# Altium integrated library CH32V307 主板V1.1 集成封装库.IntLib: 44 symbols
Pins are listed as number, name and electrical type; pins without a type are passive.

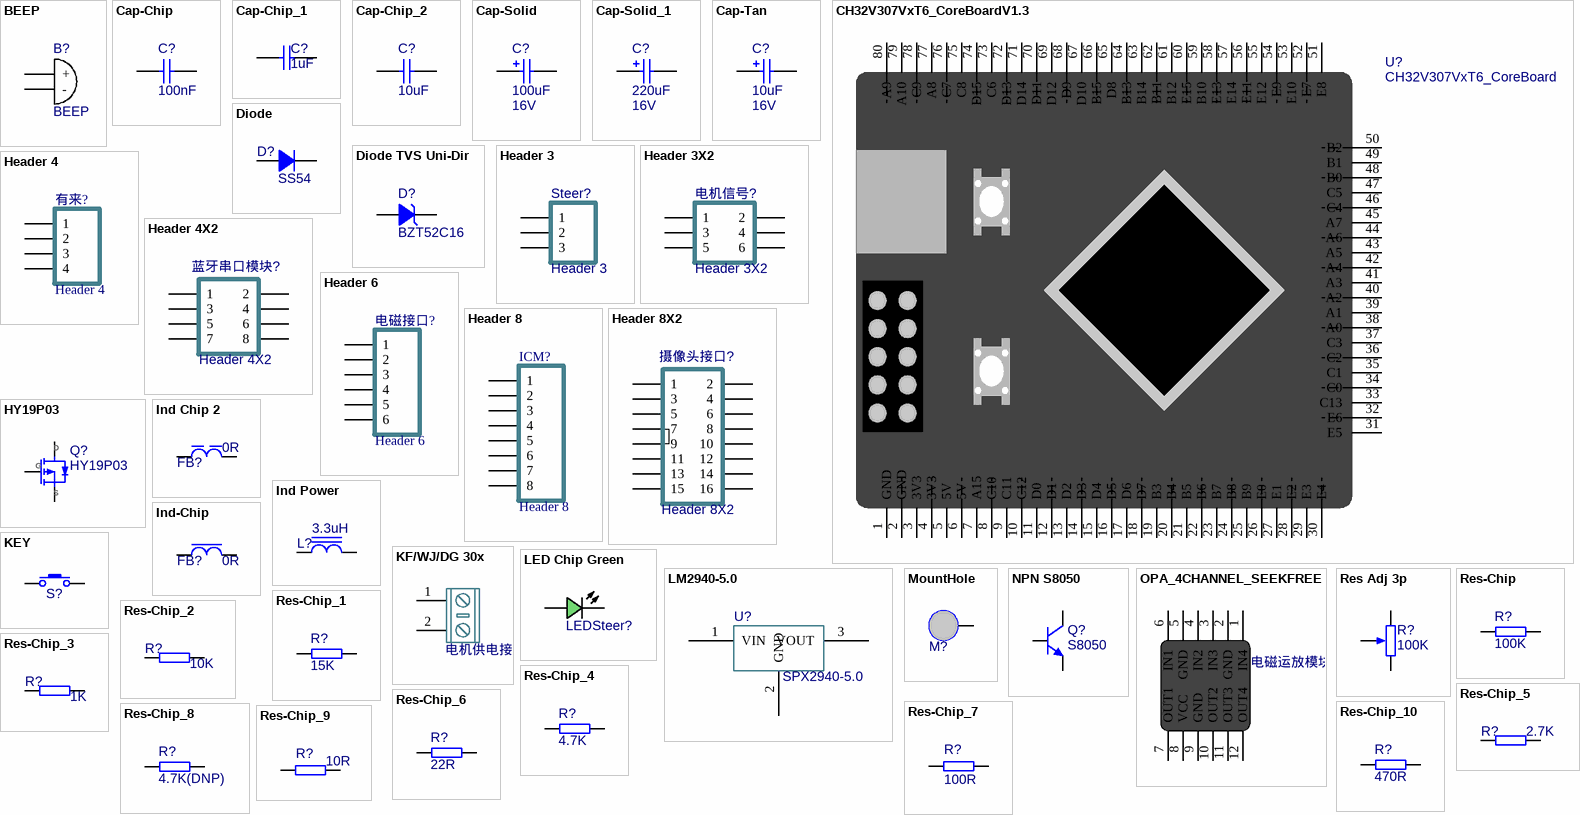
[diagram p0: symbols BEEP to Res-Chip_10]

## BEEP
designator B?
蜂鸣器
footprint BEEP 9x5.5mm
footprint BEEP 12x9.5mm
pins: 1 +, 2 -

## Cap-Chip
designator C?, comment value 100nF  (hidden comment: 100nF ±10% 50V)
贴片电容
footprint CAPC1310[0504]S (Chip Capacitor, 2-Leads, Body 1.17x1.02mm, IPC Medium Density)
footprint CAPC3216[1206]S (Chip Capacitor, Silkscreen Border,2-Leads, Body 3.20x1.60mm, IPC Medium Density)
footprint CAPC3225[1210]S (Chip Capacitor,Silkscreen Border, 2-Leads, Body 3.20x2.50mm, IPC Medium Density)
footprint CAPC4532[1812]S (Chip Capacitor, Silkscreen Border,2-Leads, Body 4.50x3.20mm, IPC Medium Density)
footprint CAPC4564[1825]S (Chip Capacitor,Silkscreen Border, 2-Leads, Body 4.50x6.40mm, IPC Medium Density)
footprint CAPC2012[0805] (Chip Capacitor, 2-Leads, Body 2.00x1.25mm, IPC Medium Density)
footprint CAPC3216[1206] (Chip Capacitor, 2-Leads, Body 3.20x1.60mm, IPC Medium Density)
footprint CAPC3225[1210] (Chip Capacitor, 2-Leads, Body 3.20x2.50mm, IPC Medium Density)
footprint CAPC4532[1812] (Chip Capacitor, 2-Leads, Body 4.50x3.20mm, IPC Medium Density)
footprint CAPC4564[1825] (Chip Capacitor, 2-Leads, Body 4.50x6.40mm, IPC Medium Density)
footprint CAPC1608[0603]-N (Chip Capacitor, 2-Leads, Body 1.60x0.80mm, IPC Medium Density)
footprint CAPC1608[0603]-L (Chip Capacitor, 2-Leads, Body 1.60x0.80mm, IPC Medium Density)
footprint CAPC1608[0603]-M (Chip Capacitor, 2-Leads, Body 1.60x0.80mm, IPC Maximum Density)
footprint CAPC1608[0603]S-L (Chip Capacitor,Silkscreen Border,2-Leads, Body 1.60x0.80mm, IPC Minimum Density)
footprint CAPC1608[0603]S-M (Chip Capacitor,Silkscreen Border,2-Leads, Body 1.60x0.80mm, IPC Maximum Density)
footprint CAPC1608[0603]S-N (Chip Capacitor,Silkscreen Border,2-Leads, Body 1.60x0.80mm, IPC Medium Density)
footprint CAPC1005[0402]-L (Chip Capacitor,Silkscreen border, 2-Leads, Body 1.00x0.50mm, IPC Medium Density)
footprint CAPC1005[0402]-M (Chip Capacitor,Silkscreen border, 2-Leads, Body 1.00x0.50mm, IPC Medium Density)
footprint CAPC1005[0402]-N (Chip Capacitor,Silkscreen border, 2-Leads, Body 1.00x0.50mm, IPC Medium Density)
footprint CAPC1005[0402]S-L (Chip Capacitor,Silkscreen border, 2-Leads, Body 1.00x0.50mm, IPC Medium Density)
footprint CAPC1005[0402]S-M (Chip Capacitor,Silkscreen border, 2-Leads, Body 1.00x0.50mm, IPC Medium Density)
footprint CAPC1005[0402]S-N (Chip Capacitor,Silkscreen border, 2-Leads, Body 1.00x0.50mm, IPC Medium Density)
footprint CAPC2012[0805]S-L (Chip Capacitor,Silkscreen Border, 2-Leads, Body 2.00x1.25mm, IPC Maximum Density)
footprint CAPC2012[0805]S-M (Chip Capacitor,Silkscreen Border, 2-Leads, Body 2.00x1.25mm, IPC Minimum Density)
footprint CAPC2012[0805]S-N (Chip Capacitor,Silkscreen Border, 2-Leads, Body 2.00x1.25mm, IPC Medium Density)
pins: 1, 2

## Cap-Chip_1
designator C?, comment value 1uF  (hidden comment: 1uF ±10% 50V)
贴片电容
footprint CAPC1310[0504]S (Chip Capacitor, 2-Leads, Body 1.17x1.02mm, IPC Medium Density)
footprint CAPC3216[1206]S (Chip Capacitor, Silkscreen Border,2-Leads, Body 3.20x1.60mm, IPC Medium Density)
footprint CAPC3225[1210]S (Chip Capacitor,Silkscreen Border, 2-Leads, Body 3.20x2.50mm, IPC Medium Density)
footprint CAPC4532[1812]S (Chip Capacitor, Silkscreen Border,2-Leads, Body 4.50x3.20mm, IPC Medium Density)
footprint CAPC4564[1825]S (Chip Capacitor,Silkscreen Border, 2-Leads, Body 4.50x6.40mm, IPC Medium Density)
footprint CAPC2012[0805] (Chip Capacitor, 2-Leads, Body 2.00x1.25mm, IPC Medium Density)
footprint CAPC3216[1206] (Chip Capacitor, 2-Leads, Body 3.20x1.60mm, IPC Medium Density)
footprint CAPC3225[1210] (Chip Capacitor, 2-Leads, Body 3.20x2.50mm, IPC Medium Density)
footprint CAPC4532[1812] (Chip Capacitor, 2-Leads, Body 4.50x3.20mm, IPC Medium Density)
footprint CAPC4564[1825] (Chip Capacitor, 2-Leads, Body 4.50x6.40mm, IPC Medium Density)
footprint CAPC1608[0603]-N (Chip Capacitor, 2-Leads, Body 1.60x0.80mm, IPC Medium Density)
footprint CAPC1608[0603]-L (Chip Capacitor, 2-Leads, Body 1.60x0.80mm, IPC Medium Density)
footprint CAPC1608[0603]-M (Chip Capacitor, 2-Leads, Body 1.60x0.80mm, IPC Maximum Density)
footprint CAPC1608[0603]S-L (Chip Capacitor,Silkscreen Border,2-Leads, Body 1.60x0.80mm, IPC Minimum Density)
footprint CAPC1608[0603]S-M (Chip Capacitor,Silkscreen Border,2-Leads, Body 1.60x0.80mm, IPC Maximum Density)
footprint CAPC1608[0603]S-N (Chip Capacitor,Silkscreen Border,2-Leads, Body 1.60x0.80mm, IPC Medium Density)
footprint CAPC1005[0402]-L (Chip Capacitor,Silkscreen border, 2-Leads, Body 1.00x0.50mm, IPC Medium Density)
footprint CAPC1005[0402]-M (Chip Capacitor,Silkscreen border, 2-Leads, Body 1.00x0.50mm, IPC Medium Density)
footprint CAPC1005[0402]-N (Chip Capacitor,Silkscreen border, 2-Leads, Body 1.00x0.50mm, IPC Medium Density)
footprint CAPC1005[0402]S-L (Chip Capacitor,Silkscreen border, 2-Leads, Body 1.00x0.50mm, IPC Medium Density)
footprint CAPC1005[0402]S-M (Chip Capacitor,Silkscreen border, 2-Leads, Body 1.00x0.50mm, IPC Medium Density)
footprint CAPC1005[0402]S-N (Chip Capacitor,Silkscreen border, 2-Leads, Body 1.00x0.50mm, IPC Medium Density)
footprint CAPC2012[0805]S-L (Chip Capacitor,Silkscreen Border, 2-Leads, Body 2.00x1.25mm, IPC Maximum Density)
footprint CAPC2012[0805]S-M (Chip Capacitor,Silkscreen Border, 2-Leads, Body 2.00x1.25mm, IPC Minimum Density)
footprint CAPC2012[0805]S-N (Chip Capacitor,Silkscreen Border, 2-Leads, Body 2.00x1.25mm, IPC Medium Density)
pins: 1, 2

## Cap-Chip_2
designator C?, comment value 10uF  (hidden comment: 10uF ±10% 50V)
贴片电容
footprint CAPC1310[0504]S (Chip Capacitor, 2-Leads, Body 1.17x1.02mm, IPC Medium Density)
footprint CAPC3216[1206]S (Chip Capacitor, Silkscreen Border,2-Leads, Body 3.20x1.60mm, IPC Medium Density)
footprint CAPC3225[1210]S (Chip Capacitor,Silkscreen Border, 2-Leads, Body 3.20x2.50mm, IPC Medium Density)
footprint CAPC4532[1812]S (Chip Capacitor, Silkscreen Border,2-Leads, Body 4.50x3.20mm, IPC Medium Density)
footprint CAPC4564[1825]S (Chip Capacitor,Silkscreen Border, 2-Leads, Body 4.50x6.40mm, IPC Medium Density)
footprint CAPC2012[0805] (Chip Capacitor, 2-Leads, Body 2.00x1.25mm, IPC Medium Density)
footprint CAPC3216[1206] (Chip Capacitor, 2-Leads, Body 3.20x1.60mm, IPC Medium Density)
footprint CAPC3225[1210] (Chip Capacitor, 2-Leads, Body 3.20x2.50mm, IPC Medium Density)
footprint CAPC4532[1812] (Chip Capacitor, 2-Leads, Body 4.50x3.20mm, IPC Medium Density)
footprint CAPC4564[1825] (Chip Capacitor, 2-Leads, Body 4.50x6.40mm, IPC Medium Density)
footprint CAPC1608[0603]-N (Chip Capacitor, 2-Leads, Body 1.60x0.80mm, IPC Medium Density)
footprint CAPC1608[0603]-L (Chip Capacitor, 2-Leads, Body 1.60x0.80mm, IPC Medium Density)
footprint CAPC1608[0603]-M (Chip Capacitor, 2-Leads, Body 1.60x0.80mm, IPC Maximum Density)
footprint CAPC1608[0603]S-L (Chip Capacitor,Silkscreen Border,2-Leads, Body 1.60x0.80mm, IPC Minimum Density)
footprint CAPC1608[0603]S-M (Chip Capacitor,Silkscreen Border,2-Leads, Body 1.60x0.80mm, IPC Maximum Density)
footprint CAPC1608[0603]S-N (Chip Capacitor,Silkscreen Border,2-Leads, Body 1.60x0.80mm, IPC Medium Density)
footprint CAPC1005[0402]-L (Chip Capacitor,Silkscreen border, 2-Leads, Body 1.00x0.50mm, IPC Medium Density)
footprint CAPC1005[0402]-M (Chip Capacitor,Silkscreen border, 2-Leads, Body 1.00x0.50mm, IPC Medium Density)
footprint CAPC1005[0402]-N (Chip Capacitor,Silkscreen border, 2-Leads, Body 1.00x0.50mm, IPC Medium Density)
footprint CAPC1005[0402]S-L (Chip Capacitor,Silkscreen border, 2-Leads, Body 1.00x0.50mm, IPC Medium Density)
footprint CAPC1005[0402]S-M (Chip Capacitor,Silkscreen border, 2-Leads, Body 1.00x0.50mm, IPC Medium Density)
footprint CAPC1005[0402]S-N (Chip Capacitor,Silkscreen border, 2-Leads, Body 1.00x0.50mm, IPC Medium Density)
footprint CAPC2012[0805]S-L (Chip Capacitor,Silkscreen Border, 2-Leads, Body 2.00x1.25mm, IPC Maximum Density)
footprint CAPC2012[0805]S-M (Chip Capacitor,Silkscreen Border, 2-Leads, Body 2.00x1.25mm, IPC Minimum Density)
footprint CAPC2012[0805]S-N (Chip Capacitor,Silkscreen Border, 2-Leads, Body 2.00x1.25mm, IPC Medium Density)
pins: 1, 2

## Cap-Solid
designator C?, comment value 100uF  Voltage: 16V  (hidden comment: 100uF 16V)
Polarized Capacitor (Radial)
footprint CAPS4 (Solid Electorlytic Capacitor, B-type Footprint, 4mm Diameter, 5.5mm Height)
footprint CAPS5 (Solid Electorlytic Capacitor, D-type Footprint, 5mm Diameter, 5.5mm Height)
footprint CAPS6.3 (Solid Electorlytic Capacitor, E-type Footprint, 6.3mm Diameter, 5.5mm Height)
footprint CAPS8 (Solid Electorlytic Capacitor, G-type Footprint, 8mm Diameter, 10mm Height)
footprint CAPS10 (Solid Electorlytic Capacitor, H-type Footprint, 10mm Diameter, 10mm Height)
pins: 1, 2

## Cap-Solid_1
designator C?, comment value 220uF  Voltage: 16V  (hidden comment: 220uF 16V)
Polarized Capacitor (Radial)
footprint CAPS4 (Solid Electorlytic Capacitor, B-type Footprint, 4mm Diameter, 5.5mm Height)
footprint CAPS5 (Solid Electorlytic Capacitor, D-type Footprint, 5mm Diameter, 5.5mm Height)
footprint CAPS6.3 (Solid Electorlytic Capacitor, E-type Footprint, 6.3mm Diameter, 5.5mm Height)
footprint CAPS8 (Solid Electorlytic Capacitor, G-type Footprint, 8mm Diameter, 10mm Height)
footprint CAPS10 (Solid Electorlytic Capacitor, H-type Footprint, 10mm Diameter, 10mm Height)
pins: 1, 2

## Cap-Tan
designator C?, comment value 10uF  Voltage: 16V  (hidden comment: 10uF 16V)
Tantalum Capacitor
footprint CAPT3216 (Molded (Tantalum) Capacitor, 2-Leads, Body 3.20x1.60mm, IPC Medium Density)
footprint CAPT3528 (Molded Tantalum Capacitor, 2-Leads, Body 3.50x2.80mm, IPC Medium Density)
footprint CAPT6032 (Molded Tantalum Capacitor, 2-Leads, Body 6.00x3.20mm, IPC Medium Density)
footprint CAPT7343 (Molded Tantalum Capacitor, 2-Leads, Body 7.30x4.30mm, IPC Medium Density)
footprint CAPT7361 (Molded Tantalum Capacitor, 2-Leads, Body 7.30x6.10mm, IPC Medium Density)
pins: 1, 2

## CH32V307VxT6_CoreBoardV1.3
designator U?, comment CH32V307VxT6_CoreBoard
CH32V307VxT6_CoreBoardV1.3
footprint CH32V307VxT6_CoreBoard (逐飞科技CH32V307VxT6核心板)
pins: 1 GND, 2 GND, 3 3V3, 4 3V3, 5 5V, 6 5V, 7 A15, 8 C10, 9 C11, 10 C12, 11 D0, 12 D1, 13 D2, 14 D3, 15 D4, 16 D5, 17 D6, 18 D7, 19 B3, 20 B4, 21 B5, 22 B6, 23 B7, 24 B8, 25 B9, 26 E0, 27 E1, 28 E2, 29 E3, 30 E4, 31 E5, 32 E6, 33 C13, 34 C0, 35 C1, 36 C2, 37 C3, 38 A0, 39 A1, 40 A2, 41 A3, 42 A4, 43 A5, 44 A6, 45 A7, 46 C4, 47 C5, 48 B0, 49 B1, 50 B2, 51 E8, 52 E7, 53 E10, 54 E9, 55 E12, 56 E11, 57 E14, 58 E13, 59 B10, 60 E15, 61 B12, 62 B11, 63 B14, 64 B13, 65 D8, 66 B15, 67 D10, 68 D9, 69 D12, 70 D11, 71 D14, 72 D13, 73 C6, 74 D15, 75 C8, 76 C7, 77 A8, 78 C9, 79 A10, 80 A9

## Diode
designator D?, comment SS54
普通二极管 Diode; Imax: 500mA
footprint SMB[DO-214AA] (Molded Diode, 2-Leads, Body 5.30x3.55mm, IPC Medium Density)
footprint SMC[DO-214AB] (Molded Diode, 2-Leads, Body 7.94x5.90mm, IPC Medium Density)
footprint SMA[DO-214AC] (Molded Diode, 2-Leads, Body 5.00x2.49mm, IPC Medium Density)
footprint SOD-123-FL (SOD Diode;2.70mm W X 1.60mm L X 1.35mm H body)
footprint SOD-123-M (SOD Diode;2.70mm W X 1.60mm L X 1.35mm H body)
footprint SOD-323 (SOD Diode;1.65mm W X 1.24mm L X 1.16mm H body)
footprint SOD-523-L (SODFL Diode;1.20mm W X 0.80mm L X 0.70mm H body)
footprint SOD-523-M (SODFL Diode;1.20mm W X 0.80mm L X 0.70mm H body)
footprint SOD-123-L (SOD Diode;2.70mm W X 1.60mm L X 1.35mm H body)
pins: A, K

## Diode TVS Uni-Dir
designator D?, comment BZT52C16
TRANSIENT VOLTAGE  SUPPRESSOR DIODE; Imax: 500mA
footprint DO-41 (Diode,Axial;8.30mm C X 0.70mm W 4.60mm L X 2.40mm Dia)
footprint SMA[DO-214AC] (Molded Diode, 2-Leads, Body 5.00x2.49mm, IPC Medium Density)
footprint SMB[DO-214AA] (Molded Diode, 2-Leads, Body 5.30x3.55mm, IPC Medium Density)
footprint SMC[DO-214AB] (Molded Diode, 2-Leads, Body 7.94x5.90mm, IPC Medium Density)
footprint SOD-123-FL (SOD Diode;2.70mm W X 1.60mm L X 1.35mm H body)
footprint SOD-323 (SOD Diode;1.65mm W X 1.24mm L X 1.16mm H body)
footprint SOD-123-L (SOD Diode;2.70mm W X 1.60mm L X 1.35mm H body)
footprint SOD-523-L (SODFL Diode;1.20mm W X 0.80mm L X 0.70mm H body)
footprint SOD-123-M (SOD Diode;2.70mm W X 1.60mm L X 1.35mm H body)
footprint SOD-523-M (SODFL Diode;1.20mm W X 0.80mm L X 0.70mm H body)
pins: A, K

## Header 3
designator Steer?
Header, 3-Pin
footprint HDR1X3 (Connector; Header; 3 Position)
signal-integrity model Connector
footprint XH2.54-3
footprint VH3.96-3
footprint PH2.0-3
footprint GH1.25T-3P (线对板 1.25mm间距 3P 表贴连接座)
footprint XH2.54-3-L (XH2.54 卧式 三针白色插座)
footprint XH2.54-WS-3P (长：12.5mm，宽：8mm，高：6.1mm   淘宝ID:黄晶宝石   店铺网址:https://shop463601444.taobao.com)
pins: 1, 2, 3

## Header 3X2
designator 电机信号?
Header, 3-Pin, Dual row
signal-integrity model Connector
footprint HDR2X3 (Connector; Header; 3x2 Position)
footprint HDR2X3-M-SMT
footprint HDR2X3-F-SMT (2x3pin, 2.54mm间距, SMT, 直排母)
pins: 1, 2, 3, 4, 5, 6

## Header 4
designator 有来?
Header, 4-Pin
signal-integrity model Connector
footprint HDR1X4 (Connector; Header; 4 Position)
footprint XH2.54-4
footprint VH3.96-4
footprint PH2.0-4 (PH2.0 4 pin)
footprint HDR1X4_Download (4pin下载接口)
footprint HDR1X4-NS (2.54间距, 4Pin, 直插排针, 无丝印)
footprint GH1.25T-4P (线对板 1.25mm间距 4P 表贴连接座)
footprint XH2.54-4-L (XH2.54 卧式 四针白色插座)
footprint HDR1X4-TP (2.54mm间距,表面焊盘)
footprint HDR1X4-TP-NS (2.54mm间距,表面焊盘 无丝印)
pins: 1, 2, 3, 4

## Header 4X2
designator 蓝牙串口模块?
Header, 4-Pin, Dual row
footprint HDR2X4 (Connector; Header; 4x2 Position)
signal-integrity model Connector
footprint Female-Header-2.54-SMD-8
footprint HDR2X4-M-SMT (2x4pin, 2.54mm间距, SMT, 直排针)
footprint HDR2X4-F-SMT (2x4pin, 2.54mm间距, SMT, 直排母)
pins: 1, 2, 3, 4, 5, 6, 7, 8

## Header 6
designator 电磁接口?
Header, 6-Pin
footprint HDR1X6 (Connector; Header; 6 Position)
signal-integrity model Connector
footprint PH2.0-6 (PH2.0 9 pin)
footprint XH2.54-6
footprint VH3.96-6
footprint GH1.25T-6P (线对板 1.25mm间距 6P 表贴连接座)
footprint ZH1.5-WF-6P
pins: 1, 2, 3, 4, 5, 6

## Header 8
designator ICM?
Header, 8-Pin
footprint HDR1X8 (Connector; Header; 8 Position)
signal-integrity model Connector
footprint XH2.54V-8
footprint XH2.54-8
footprint VH3.96-8
footprint PH2.0-8 (PH2.0 9 pin)
footprint GH1.25T-8P (线对板 1.25mm间距 8P 表贴连接座)
pins: 1, 2, 3, 4, 5, 6, 7, 8

## Header 8X2
designator 摄像头接口?
Header, 8-Pin, Dual row
footprint HDR2X8 (Connector; Header; 8x2 Position)
signal-integrity model Connector
footprint IDC2.54-16
footprint HDR2X8-M-SMT (2x8pin, 2.54mm间距, SMT, 直排针)
footprint HDR2X8-F-SMT (2x8pin, 2.54mm间距, SMT, 直排母)
pins: 1, 2, 3, 4, 5, 6, 7, 8, 9, 10, 11, 12, 13, 14, 15, 16

## HY19P03
designator Q?
HY19P03 P-Channel MOSFET
footprint TO-252AA (D-PAK, 4-Leads, Body 6.1x6.5mm, Pitch 2.28mm, Lead Span 9.8mm, IPC Low Density)
pins: 1 D, 2 G, 3 S

## Ind Chip 2
designator FB?, comment 0R
Chip Inductor, Ferrite-Core, Silkscreen Border; Imax: 50mA; DCR: .1m
footprint INDC2012[0805]S (Chip Inductor,Silkscreen Border, 2-Leads, Body 2.00x0.90mm, IPC Medium Density)
pins: 1, 2

## Ind Power
designator L?, comment 3.3uH
Power Inductor, Ferrite-Core; Imax: 50mA; DCR: .5m
footprint CD31
footprint CD32
footprint CD42
footprint CD43
footprint CD52
footprint CD53
footprint CD54
footprint CD73
footprint CD75
footprint CD104
footprint CD105
footprint CD106
footprint 127 Shielded 12.5*12.5*7 (12.5mmx12.5mmx7mm 屏蔽电感)
footprint 0630 TPC 7*7*3 (12mmx12mmx6.5mm 一体成型功率电感)
footprint 1050 TPC 10*10*5 (12mmx12mmx6.5mm 一体成型功率电感)
footprint 1265 TPC 12*12*6.5 (12mmx12mmx6.5mm 一体成型功率电感)
pins: 1, 2

## Ind-Chip
designator FB?, comment 0R
Chip Inductor, Ferrite-Core, Silkscreen Border; Imax: 500mA; DCR: .1m
footprint INDC1608[0603]S (Not in IPC, Chip Inductor,Silkscreen Border, 2-Leads, Body 1.60x0.80mm, IPC Medium Density)
footprint INDC2012[0805]S (Chip Inductor,Silkscreen Border, 2-Leads, Body 2.00x0.90mm, IPC Medium Density)
footprint INDC3216[1206]S (Chip Inductor,Silkscreen Border, 2-Leads, Body 3.20x1.60mm, IPC Medium Density)
footprint INDC4509[1806]S (Chip Inductor,Silkscreen Border, 2-Leads, Body 4.50x0.90mm, IPC Medium Density)
footprint INDC1005[0402] (Chip Inductor, 2-Leads, Body 1.00x0.50mm, IPC Medium Density)
footprint INDC1608[0603] (Chip Inductor, 2-Leads, Body 1.60x0.80mm, IPC Medium Density)
footprint INDC2012[0805] (Chip Inductor, 2-Leads, Body 2.00x0.90mm, IPC Medium Density)
footprint INDC3216[1206] (Chip Inductor, 2-Leads, Body 3.20x1.60mm, IPC Medium Density)
footprint INDC3225[1210] (Capacitor,non-polarized,Chip;3.20mm L X 2.50mm W X 1.35mm H)
footprint INDC3216[1206] (Chip Inductor, 2-Leads, Body 3.20x1.60mm, IPC Medium Density)
pins: 1, 2

## KEY
designator S?, comment Button  (value not drawn)
按键
footprint KEY-2-SMD-3*4 (龟仔按键 3*4)
footprint KEY-4-DIP-6*6 (6x6 直插按键封装)
footprint PTS810-3*4-CurvePin (3*4 白色 汽车遥控器贴片按键 包脚)
footprint KEY-2-SMD-3*6-L (3x6贴片按键 高密度)
footprint KEY-2-SMD-3*6-M (3x6贴片按键 低密度)
footprint KEY-4-SMD-6*6 (6x6贴片按键封装)
footprint KEY-2-SMD-Side-3*6*3.5 (7.6x3.5mm 侧按按键)
footprint KEY-4-SMD-12*12 (6x6贴片按键封装)
footprint TS-1809SM-A (3*3.5 贴片4脚按键 (TS-A015))
pins: 1, 2

## KF/WJ/DG 30x
designator DCOUT?, comment 电机供电接口
接线端子 2Pin
footprint KF/WJ/DG 301-2p-5.0mm (2P 5.08mm间距 接线端子)
pins: 1, 2

## LED Chip Green
designator LEDSteer?, comment 翠绿贴片LED  (value not drawn)
footprint LEDC1608(0603) (LED,Chip;1.60mm L X 0.80mm W X 0.80mm H)
footprint LEDC2012(0805) (LED,Chip;2.00mm L X 1.25mm W X 1.20mm H)
footprint LEDC3216(1206) (LED,Chip;3.20mm L X 1.60mm W X 1.30mm H)
footprint LEDC1608(0603)-L (LED,Chip;1.60mm L X 0.80mm W X 0.80mm H)
footprint LEDC2012(0805)-L (LED,Chip;2.00mm L X 1.25mm W X 1.20mm H)
footprint LEDC3216(1204) (LED,Chip;3.20mm L X 1.60mm W X 1.30mm H)
footprint LEDC3528-2 (3528 2脚 贴片LED)
pins: A, C

## LM2940-5.0
designator U?, comment SPX2940-5.0
5V LDO TO-263-3
footprint TO-263-3
pins: 1 VIN, 2 GND, 3 VOUT

## MountHole
designator M?  (value not drawn)  (no BOM)
固定孔
footprint M3-MountHole
footprint M3-MountSlot (M3-MountHole)
footprint M3-MountHole-Plated (M3-MountHole)
footprint M3-MountSlot-Plated (M3-MountHole)
footprint M3-MountHole-4mm (M3-MountHole)
footprint M3-MountHole-5mm (M3-MountHole)
footprint M3-MountHole-6mm (M3-MountHole)
footprint M3-MountHole-7mm (M3-MountHole)
footprint M3-MountHole-8mm (M3-MountHole)
footprint M3-MountHole-9mm (M3-MountHole)
footprint M3-MountHole-10mm (M3-MountHole)
footprint M3-MountHole-11mm (M3-MountHole)
footprint M3-MountHole-12mm (M3-MountHole)
footprint M3-MountHole-13mm (M3-MountHole)
footprint M3-MountHole-14mm (M3-MountHole)
footprint M3-MountHole-15mm (M3-MountHole)
footprint M3-MountHole-16mm (M3-MountHole)
footprint M3-MountHole-17mm (M3-MountHole)
footprint M3-MountHole-18mm (M3-MountHole)
footprint M3-MountHole-19mm (M3-MountHole)
footprint M3-MountHole-20mm (M3-MountHole)
footprint M3-MountHole-Plated-4MM (M3-MountHole)
footprint M3-MountHole-Plated-5MM (M3-MountHole)
footprint M3-MountHole-Plated-6MM (M3-MountHole)
footprint M3-MountHole-Plated-7MM (M3-MountHole)
footprint M3-MountHole-Plated-8MM (M3-MountHole)
footprint M3-MountHole-Plated-9MM (M3-MountHole)
footprint M3-MountHole-Plated-10MM (M3-MountHole)
footprint M3-MountHole-Plated-11MM (M3-MountHole)
footprint M3-MountHole-Plated-12MM (M3-MountHole)
footprint M3-MountHole-Plated-13MM (M3-MountHole)
footprint M3-MountHole-Plated-14MM (M3-MountHole)
footprint M3-MountHole-Plated-15MM (M3-MountHole)
footprint M3-MountHole-Plated-16MM (M3-MountHole)
footprint M3-MountHole-Plated-17MM (M3-MountHole)
footprint M3-MountHole-Plated-18MM (M3-MountHole)
footprint M3-MountHole-Plated-19MM (M3-MountHole)
footprint M3-MountHole-Plated-20MM (M3-MountHole)
pins: 1

## NPN S8050
designator Q?, comment S8050
Discrete NPN Bipolar Transistor
footprint SOT-23 (SOT23, 3-Leads, Body 2.90x2.40mm, Pitch 0.95mm, IPC Medium Density)
pins: 1 B, 2 E, 3 C

## OPA_4CHANNEL_SEEKFREE
designator 电磁运放模块?, comment OPA_MOD  (value not drawn)  (no BOM)
OPA module
footprint SEEKFREE_4CHANEL_OPAMOD
pins: 1 IN4, 2 GND, 3 IN3, 4 IN2, 5 GND, 6 IN1, 7 OUT1, 8 VCC, 9 GND, 10 OUT2, 11 OUT3, 12 OUT4

## Res Adj 3p
designator R?, comment 100K
可调电阻
footprint RESPOT3296 (Precise Multi-Winding Adjustable Resistor)
footprint RESPOTSMALL (Small Pot)
pins: 1 TOP, 2 BOT, ADJ

## Res-Chip
designator R?, comment value 100K  (hidden comment: 100K ±1%)
贴片电阻
footprint RESC3225[1210]S (Silkscreen Outside, Chip Resistor, 2-Leads, Body 3.20x2.49mm, IPC Medium Density)
footprint RESC5025[2010]S (Silkscreen Outside, Chip Resistor, 2-Leads, Body 5.00x2.50mm, IPC Medium Density)
footprint RESC6332[2512]S (Silkscreen Outside, Chip Resistor, 2-Leads, Body 6.30x3.20mm, IPC Medium Density)
footprint RESC5025[2010] (Chip Resistor, 2-Leads, Body 5.00x2.50mm, IPC Medium Density)
footprint RESC6332[2512] (Chip Resistor, 2-Leads, Body 6.30x3.20mm, IPC Medium Density)
footprint RESC3225[1210] (Chip Resistor, 2-Leads, Body 3.20x2.49mm, IPC Medium Density)
footprint RESC3216[1206] (Chip Resistor, 2-Leads, Body 3.20x1.60mm, IPC Medium Density)
footprint RESC2012[0805] (Chip Resistor, 2-Leads, Body 2.00x1.25mm, IPC Medium Density)
footprint RESC1608[0603]-M (Chip Resistor, 2-Leads, Body 1.60x0.82mm, IPC Maximum Density)
footprint RESC1608[0603]-L (Chip Resistor, 2-Leads, Body 1.60x0.82mm, IPC Minimum Density)
footprint RESC1608[0603]-N (Chip Resistor, 2-Leads, Body 1.60x0.82mm, IPC Medium Density)
footprint RESC1608[0603]S-L (Silkscreen Outside, Chip Resistor, 2-Leads, Body 1.60x0.82mm, IPC Minimum Density)
footprint RESC1608[0603]S-M (Silkscreen Outside, Chip Resistor, 2-Leads, Body 1.60x0.82mm, IPC Maximum Density)
footprint RESC1608[0603]S-N (Silkscreen Outside, Chip Resistor, 2-Leads, Body 1.60x0.82mm, IPC Medium Density)
footprint RESC1005[0402]-L (0402贴片电阻 无丝印 2脚 1.00x0.50mm，IPC高密度)
footprint RESC1005[0402]-N (0402贴片电阻 无丝印 2脚 1.00x0.50mm，IPC中密度)
footprint RESC1005[0402]-M (0402贴片电阻 无丝印 2脚 1.00x0.50mm，IPC低密度)
footprint RESC1005[0402]S-L (0402贴片电阻 有丝印 2脚 1.00x0.50mm，IPC高密度)
footprint RESC1005[0402]S-M (0402贴片电阻 有丝印 2脚 1.00x0.50mm，IPC低密度)
footprint RESC1005[0402]S-N (0402贴片电阻 有丝印 2脚 1.00x0.50mm，IPC中等密度)
footprint RESC2012[0805]S-L (Silkscreen Outside, Chip Resistor, 2-Leads, Body 2.00x1.25mm, IPC Medium Density)
footprint RESC2012[0805]S-M (Silkscreen Outside, Chip Resistor, 2-Leads, Body 2.00x1.25mm, IPC Medium Density)
footprint RESC2012[0805]S-N (Silkscreen Outside, Chip Resistor, 2-Leads, Body 2.00x1.25mm, IPC Medium Density)
footprint RESC3216[1206]S-L (Silkscreen Outside, Chip Resistor, 2-Leads, Body 3.20x1.60mm, IPC Medium Density)
footprint RESC3216[1206]S-M (Silkscreen Outside, Chip Resistor, 2-Leads, Body 3.20x1.60mm, IPC Medium Density)
footprint RESC3216[1206]S-N (Silkscreen Outside, Chip Resistor, 2-Leads, Body 3.20x1.60mm, IPC Medium Density)
pins: 1, 2
1 alternate drawing of the same symbol

## Res-Chip_1
designator R?, comment value 15K  (hidden comment: 15K ±1%)
贴片电阻
footprint RESC3225[1210]S (Silkscreen Outside, Chip Resistor, 2-Leads, Body 3.20x2.49mm, IPC Medium Density)
footprint RESC5025[2010]S (Silkscreen Outside, Chip Resistor, 2-Leads, Body 5.00x2.50mm, IPC Medium Density)
footprint RESC6332[2512]S (Silkscreen Outside, Chip Resistor, 2-Leads, Body 6.30x3.20mm, IPC Medium Density)
footprint RESC5025[2010] (Chip Resistor, 2-Leads, Body 5.00x2.50mm, IPC Medium Density)
footprint RESC6332[2512] (Chip Resistor, 2-Leads, Body 6.30x3.20mm, IPC Medium Density)
footprint RESC3225[1210] (Chip Resistor, 2-Leads, Body 3.20x2.49mm, IPC Medium Density)
footprint RESC3216[1206] (Chip Resistor, 2-Leads, Body 3.20x1.60mm, IPC Medium Density)
footprint RESC2012[0805] (Chip Resistor, 2-Leads, Body 2.00x1.25mm, IPC Medium Density)
footprint RESC1608[0603]-M (Chip Resistor, 2-Leads, Body 1.60x0.82mm, IPC Maximum Density)
footprint RESC1608[0603]-L (Chip Resistor, 2-Leads, Body 1.60x0.82mm, IPC Minimum Density)
footprint RESC1608[0603]-N (Chip Resistor, 2-Leads, Body 1.60x0.82mm, IPC Medium Density)
footprint RESC1608[0603]S-L (Silkscreen Outside, Chip Resistor, 2-Leads, Body 1.60x0.82mm, IPC Minimum Density)
footprint RESC1608[0603]S-M (Silkscreen Outside, Chip Resistor, 2-Leads, Body 1.60x0.82mm, IPC Maximum Density)
footprint RESC1608[0603]S-N (Silkscreen Outside, Chip Resistor, 2-Leads, Body 1.60x0.82mm, IPC Medium Density)
footprint RESC1005[0402]-L (0402贴片电阻 无丝印 2脚 1.00x0.50mm，IPC高密度)
footprint RESC1005[0402]-N (0402贴片电阻 无丝印 2脚 1.00x0.50mm，IPC中密度)
footprint RESC1005[0402]-M (0402贴片电阻 无丝印 2脚 1.00x0.50mm，IPC低密度)
footprint RESC1005[0402]S-L (0402贴片电阻 有丝印 2脚 1.00x0.50mm，IPC高密度)
footprint RESC1005[0402]S-M (0402贴片电阻 有丝印 2脚 1.00x0.50mm，IPC低密度)
footprint RESC1005[0402]S-N (0402贴片电阻 有丝印 2脚 1.00x0.50mm，IPC中等密度)
footprint RESC2012[0805]S-L (Silkscreen Outside, Chip Resistor, 2-Leads, Body 2.00x1.25mm, IPC Medium Density)
footprint RESC2012[0805]S-M (Silkscreen Outside, Chip Resistor, 2-Leads, Body 2.00x1.25mm, IPC Medium Density)
footprint RESC2012[0805]S-N (Silkscreen Outside, Chip Resistor, 2-Leads, Body 2.00x1.25mm, IPC Medium Density)
footprint RESC3216[1206]S-L (Silkscreen Outside, Chip Resistor, 2-Leads, Body 3.20x1.60mm, IPC Medium Density)
footprint RESC3216[1206]S-M (Silkscreen Outside, Chip Resistor, 2-Leads, Body 3.20x1.60mm, IPC Medium Density)
footprint RESC3216[1206]S-N (Silkscreen Outside, Chip Resistor, 2-Leads, Body 3.20x1.60mm, IPC Medium Density)
pins: 1, 2
1 alternate drawing of the same symbol

## Res-Chip_2
designator R?, comment value 10K  (hidden comment: 10K ±1%)
贴片电阻
footprint RESC3225[1210]S (Silkscreen Outside, Chip Resistor, 2-Leads, Body 3.20x2.49mm, IPC Medium Density)
footprint RESC5025[2010]S (Silkscreen Outside, Chip Resistor, 2-Leads, Body 5.00x2.50mm, IPC Medium Density)
footprint RESC6332[2512]S (Silkscreen Outside, Chip Resistor, 2-Leads, Body 6.30x3.20mm, IPC Medium Density)
footprint RESC5025[2010] (Chip Resistor, 2-Leads, Body 5.00x2.50mm, IPC Medium Density)
footprint RESC6332[2512] (Chip Resistor, 2-Leads, Body 6.30x3.20mm, IPC Medium Density)
footprint RESC3225[1210] (Chip Resistor, 2-Leads, Body 3.20x2.49mm, IPC Medium Density)
footprint RESC3216[1206] (Chip Resistor, 2-Leads, Body 3.20x1.60mm, IPC Medium Density)
footprint RESC2012[0805] (Chip Resistor, 2-Leads, Body 2.00x1.25mm, IPC Medium Density)
footprint RESC1608[0603]-M (Chip Resistor, 2-Leads, Body 1.60x0.82mm, IPC Maximum Density)
footprint RESC1608[0603]-L (Chip Resistor, 2-Leads, Body 1.60x0.82mm, IPC Minimum Density)
footprint RESC1608[0603]-N (Chip Resistor, 2-Leads, Body 1.60x0.82mm, IPC Medium Density)
footprint RESC1608[0603]S-L (Silkscreen Outside, Chip Resistor, 2-Leads, Body 1.60x0.82mm, IPC Minimum Density)
footprint RESC1608[0603]S-M (Silkscreen Outside, Chip Resistor, 2-Leads, Body 1.60x0.82mm, IPC Maximum Density)
footprint RESC1608[0603]S-N (Silkscreen Outside, Chip Resistor, 2-Leads, Body 1.60x0.82mm, IPC Medium Density)
footprint RESC1005[0402]-L (0402贴片电阻 无丝印 2脚 1.00x0.50mm，IPC高密度)
footprint RESC1005[0402]-N (0402贴片电阻 无丝印 2脚 1.00x0.50mm，IPC中密度)
footprint RESC1005[0402]-M (0402贴片电阻 无丝印 2脚 1.00x0.50mm，IPC低密度)
footprint RESC1005[0402]S-L (0402贴片电阻 有丝印 2脚 1.00x0.50mm，IPC高密度)
footprint RESC1005[0402]S-M (0402贴片电阻 有丝印 2脚 1.00x0.50mm，IPC低密度)
footprint RESC1005[0402]S-N (0402贴片电阻 有丝印 2脚 1.00x0.50mm，IPC中等密度)
footprint RESC2012[0805]S-L (Silkscreen Outside, Chip Resistor, 2-Leads, Body 2.00x1.25mm, IPC Medium Density)
footprint RESC2012[0805]S-M (Silkscreen Outside, Chip Resistor, 2-Leads, Body 2.00x1.25mm, IPC Medium Density)
footprint RESC2012[0805]S-N (Silkscreen Outside, Chip Resistor, 2-Leads, Body 2.00x1.25mm, IPC Medium Density)
footprint RESC3216[1206]S-L (Silkscreen Outside, Chip Resistor, 2-Leads, Body 3.20x1.60mm, IPC Medium Density)
footprint RESC3216[1206]S-M (Silkscreen Outside, Chip Resistor, 2-Leads, Body 3.20x1.60mm, IPC Medium Density)
footprint RESC3216[1206]S-N (Silkscreen Outside, Chip Resistor, 2-Leads, Body 3.20x1.60mm, IPC Medium Density)
pins: 1, 2
1 alternate drawing of the same symbol

## Res-Chip_3
designator R?, comment value 1K  (hidden comment: 1K ±1%)
贴片电阻
footprint RESC3225[1210]S (Silkscreen Outside, Chip Resistor, 2-Leads, Body 3.20x2.49mm, IPC Medium Density)
footprint RESC5025[2010]S (Silkscreen Outside, Chip Resistor, 2-Leads, Body 5.00x2.50mm, IPC Medium Density)
footprint RESC6332[2512]S (Silkscreen Outside, Chip Resistor, 2-Leads, Body 6.30x3.20mm, IPC Medium Density)
footprint RESC5025[2010] (Chip Resistor, 2-Leads, Body 5.00x2.50mm, IPC Medium Density)
footprint RESC6332[2512] (Chip Resistor, 2-Leads, Body 6.30x3.20mm, IPC Medium Density)
footprint RESC3225[1210] (Chip Resistor, 2-Leads, Body 3.20x2.49mm, IPC Medium Density)
footprint RESC3216[1206] (Chip Resistor, 2-Leads, Body 3.20x1.60mm, IPC Medium Density)
footprint RESC2012[0805] (Chip Resistor, 2-Leads, Body 2.00x1.25mm, IPC Medium Density)
footprint RESC1608[0603]-M (Chip Resistor, 2-Leads, Body 1.60x0.82mm, IPC Maximum Density)
footprint RESC1608[0603]-L (Chip Resistor, 2-Leads, Body 1.60x0.82mm, IPC Minimum Density)
footprint RESC1608[0603]-N (Chip Resistor, 2-Leads, Body 1.60x0.82mm, IPC Medium Density)
footprint RESC1608[0603]S-L (Silkscreen Outside, Chip Resistor, 2-Leads, Body 1.60x0.82mm, IPC Minimum Density)
footprint RESC1608[0603]S-M (Silkscreen Outside, Chip Resistor, 2-Leads, Body 1.60x0.82mm, IPC Maximum Density)
footprint RESC1608[0603]S-N (Silkscreen Outside, Chip Resistor, 2-Leads, Body 1.60x0.82mm, IPC Medium Density)
footprint RESC1005[0402]-L (0402贴片电阻 无丝印 2脚 1.00x0.50mm，IPC高密度)
footprint RESC1005[0402]-N (0402贴片电阻 无丝印 2脚 1.00x0.50mm，IPC中密度)
footprint RESC1005[0402]-M (0402贴片电阻 无丝印 2脚 1.00x0.50mm，IPC低密度)
footprint RESC1005[0402]S-L (0402贴片电阻 有丝印 2脚 1.00x0.50mm，IPC高密度)
footprint RESC1005[0402]S-M (0402贴片电阻 有丝印 2脚 1.00x0.50mm，IPC低密度)
footprint RESC1005[0402]S-N (0402贴片电阻 有丝印 2脚 1.00x0.50mm，IPC中等密度)
footprint RESC2012[0805]S-L (Silkscreen Outside, Chip Resistor, 2-Leads, Body 2.00x1.25mm, IPC Medium Density)
footprint RESC2012[0805]S-M (Silkscreen Outside, Chip Resistor, 2-Leads, Body 2.00x1.25mm, IPC Medium Density)
footprint RESC2012[0805]S-N (Silkscreen Outside, Chip Resistor, 2-Leads, Body 2.00x1.25mm, IPC Medium Density)
footprint RESC3216[1206]S-L (Silkscreen Outside, Chip Resistor, 2-Leads, Body 3.20x1.60mm, IPC Medium Density)
footprint RESC3216[1206]S-M (Silkscreen Outside, Chip Resistor, 2-Leads, Body 3.20x1.60mm, IPC Medium Density)
footprint RESC3216[1206]S-N (Silkscreen Outside, Chip Resistor, 2-Leads, Body 3.20x1.60mm, IPC Medium Density)
pins: 1, 2
1 alternate drawing of the same symbol

## Res-Chip_4
designator R?, comment value 4.7K  (hidden comment: 4.7K ±1%)
贴片电阻
footprint RESC3225[1210]S (Silkscreen Outside, Chip Resistor, 2-Leads, Body 3.20x2.49mm, IPC Medium Density)
footprint RESC5025[2010]S (Silkscreen Outside, Chip Resistor, 2-Leads, Body 5.00x2.50mm, IPC Medium Density)
footprint RESC6332[2512]S (Silkscreen Outside, Chip Resistor, 2-Leads, Body 6.30x3.20mm, IPC Medium Density)
footprint RESC5025[2010] (Chip Resistor, 2-Leads, Body 5.00x2.50mm, IPC Medium Density)
footprint RESC6332[2512] (Chip Resistor, 2-Leads, Body 6.30x3.20mm, IPC Medium Density)
footprint RESC3225[1210] (Chip Resistor, 2-Leads, Body 3.20x2.49mm, IPC Medium Density)
footprint RESC3216[1206] (Chip Resistor, 2-Leads, Body 3.20x1.60mm, IPC Medium Density)
footprint RESC2012[0805] (Chip Resistor, 2-Leads, Body 2.00x1.25mm, IPC Medium Density)
footprint RESC1608[0603]-M (Chip Resistor, 2-Leads, Body 1.60x0.82mm, IPC Maximum Density)
footprint RESC1608[0603]-L (Chip Resistor, 2-Leads, Body 1.60x0.82mm, IPC Minimum Density)
footprint RESC1608[0603]-N (Chip Resistor, 2-Leads, Body 1.60x0.82mm, IPC Medium Density)
footprint RESC1608[0603]S-L (Silkscreen Outside, Chip Resistor, 2-Leads, Body 1.60x0.82mm, IPC Minimum Density)
footprint RESC1608[0603]S-M (Silkscreen Outside, Chip Resistor, 2-Leads, Body 1.60x0.82mm, IPC Maximum Density)
footprint RESC1608[0603]S-N (Silkscreen Outside, Chip Resistor, 2-Leads, Body 1.60x0.82mm, IPC Medium Density)
footprint RESC1005[0402]-L (0402贴片电阻 无丝印 2脚 1.00x0.50mm，IPC高密度)
footprint RESC1005[0402]-N (0402贴片电阻 无丝印 2脚 1.00x0.50mm，IPC中密度)
footprint RESC1005[0402]-M (0402贴片电阻 无丝印 2脚 1.00x0.50mm，IPC低密度)
footprint RESC1005[0402]S-L (0402贴片电阻 有丝印 2脚 1.00x0.50mm，IPC高密度)
footprint RESC1005[0402]S-M (0402贴片电阻 有丝印 2脚 1.00x0.50mm，IPC低密度)
footprint RESC1005[0402]S-N (0402贴片电阻 有丝印 2脚 1.00x0.50mm，IPC中等密度)
footprint RESC2012[0805]S-L (Silkscreen Outside, Chip Resistor, 2-Leads, Body 2.00x1.25mm, IPC Medium Density)
footprint RESC2012[0805]S-M (Silkscreen Outside, Chip Resistor, 2-Leads, Body 2.00x1.25mm, IPC Medium Density)
footprint RESC2012[0805]S-N (Silkscreen Outside, Chip Resistor, 2-Leads, Body 2.00x1.25mm, IPC Medium Density)
footprint RESC3216[1206]S-L (Silkscreen Outside, Chip Resistor, 2-Leads, Body 3.20x1.60mm, IPC Medium Density)
footprint RESC3216[1206]S-M (Silkscreen Outside, Chip Resistor, 2-Leads, Body 3.20x1.60mm, IPC Medium Density)
footprint RESC3216[1206]S-N (Silkscreen Outside, Chip Resistor, 2-Leads, Body 3.20x1.60mm, IPC Medium Density)
pins: 1, 2
1 alternate drawing of the same symbol

## Res-Chip_5
designator R?, comment value 2.7K  (hidden comment: 2.7K ±1%)
贴片电阻
footprint RESC3225[1210]S (Silkscreen Outside, Chip Resistor, 2-Leads, Body 3.20x2.49mm, IPC Medium Density)
footprint RESC5025[2010]S (Silkscreen Outside, Chip Resistor, 2-Leads, Body 5.00x2.50mm, IPC Medium Density)
footprint RESC6332[2512]S (Silkscreen Outside, Chip Resistor, 2-Leads, Body 6.30x3.20mm, IPC Medium Density)
footprint RESC5025[2010] (Chip Resistor, 2-Leads, Body 5.00x2.50mm, IPC Medium Density)
footprint RESC6332[2512] (Chip Resistor, 2-Leads, Body 6.30x3.20mm, IPC Medium Density)
footprint RESC3225[1210] (Chip Resistor, 2-Leads, Body 3.20x2.49mm, IPC Medium Density)
footprint RESC3216[1206] (Chip Resistor, 2-Leads, Body 3.20x1.60mm, IPC Medium Density)
footprint RESC2012[0805] (Chip Resistor, 2-Leads, Body 2.00x1.25mm, IPC Medium Density)
footprint RESC1608[0603]-M (Chip Resistor, 2-Leads, Body 1.60x0.82mm, IPC Maximum Density)
footprint RESC1608[0603]-L (Chip Resistor, 2-Leads, Body 1.60x0.82mm, IPC Minimum Density)
footprint RESC1608[0603]-N (Chip Resistor, 2-Leads, Body 1.60x0.82mm, IPC Medium Density)
footprint RESC1608[0603]S-L (Silkscreen Outside, Chip Resistor, 2-Leads, Body 1.60x0.82mm, IPC Minimum Density)
footprint RESC1608[0603]S-M (Silkscreen Outside, Chip Resistor, 2-Leads, Body 1.60x0.82mm, IPC Maximum Density)
footprint RESC1608[0603]S-N (Silkscreen Outside, Chip Resistor, 2-Leads, Body 1.60x0.82mm, IPC Medium Density)
footprint RESC1005[0402]-L (0402贴片电阻 无丝印 2脚 1.00x0.50mm，IPC高密度)
footprint RESC1005[0402]-N (0402贴片电阻 无丝印 2脚 1.00x0.50mm，IPC中密度)
footprint RESC1005[0402]-M (0402贴片电阻 无丝印 2脚 1.00x0.50mm，IPC低密度)
footprint RESC1005[0402]S-L (0402贴片电阻 有丝印 2脚 1.00x0.50mm，IPC高密度)
footprint RESC1005[0402]S-M (0402贴片电阻 有丝印 2脚 1.00x0.50mm，IPC低密度)
footprint RESC1005[0402]S-N (0402贴片电阻 有丝印 2脚 1.00x0.50mm，IPC中等密度)
footprint RESC2012[0805]S-L (Silkscreen Outside, Chip Resistor, 2-Leads, Body 2.00x1.25mm, IPC Medium Density)
footprint RESC2012[0805]S-M (Silkscreen Outside, Chip Resistor, 2-Leads, Body 2.00x1.25mm, IPC Medium Density)
footprint RESC2012[0805]S-N (Silkscreen Outside, Chip Resistor, 2-Leads, Body 2.00x1.25mm, IPC Medium Density)
footprint RESC3216[1206]S-L (Silkscreen Outside, Chip Resistor, 2-Leads, Body 3.20x1.60mm, IPC Medium Density)
footprint RESC3216[1206]S-M (Silkscreen Outside, Chip Resistor, 2-Leads, Body 3.20x1.60mm, IPC Medium Density)
footprint RESC3216[1206]S-N (Silkscreen Outside, Chip Resistor, 2-Leads, Body 3.20x1.60mm, IPC Medium Density)
pins: 1, 2
1 alternate drawing of the same symbol

## Res-Chip_6
designator R?, comment value 22R  (hidden comment: 22R ±1%)
贴片电阻
footprint RESC3225[1210]S (Silkscreen Outside, Chip Resistor, 2-Leads, Body 3.20x2.49mm, IPC Medium Density)
footprint RESC5025[2010]S (Silkscreen Outside, Chip Resistor, 2-Leads, Body 5.00x2.50mm, IPC Medium Density)
footprint RESC6332[2512]S (Silkscreen Outside, Chip Resistor, 2-Leads, Body 6.30x3.20mm, IPC Medium Density)
footprint RESC5025[2010] (Chip Resistor, 2-Leads, Body 5.00x2.50mm, IPC Medium Density)
footprint RESC6332[2512] (Chip Resistor, 2-Leads, Body 6.30x3.20mm, IPC Medium Density)
footprint RESC3225[1210] (Chip Resistor, 2-Leads, Body 3.20x2.49mm, IPC Medium Density)
footprint RESC3216[1206] (Chip Resistor, 2-Leads, Body 3.20x1.60mm, IPC Medium Density)
footprint RESC2012[0805] (Chip Resistor, 2-Leads, Body 2.00x1.25mm, IPC Medium Density)
footprint RESC1608[0603]-M (Chip Resistor, 2-Leads, Body 1.60x0.82mm, IPC Maximum Density)
footprint RESC1608[0603]-L (Chip Resistor, 2-Leads, Body 1.60x0.82mm, IPC Minimum Density)
footprint RESC1608[0603]-N (Chip Resistor, 2-Leads, Body 1.60x0.82mm, IPC Medium Density)
footprint RESC1608[0603]S-L (Silkscreen Outside, Chip Resistor, 2-Leads, Body 1.60x0.82mm, IPC Minimum Density)
footprint RESC1608[0603]S-M (Silkscreen Outside, Chip Resistor, 2-Leads, Body 1.60x0.82mm, IPC Maximum Density)
footprint RESC1608[0603]S-N (Silkscreen Outside, Chip Resistor, 2-Leads, Body 1.60x0.82mm, IPC Medium Density)
footprint RESC1005[0402]-L (0402贴片电阻 无丝印 2脚 1.00x0.50mm，IPC高密度)
footprint RESC1005[0402]-N (0402贴片电阻 无丝印 2脚 1.00x0.50mm，IPC中密度)
footprint RESC1005[0402]-M (0402贴片电阻 无丝印 2脚 1.00x0.50mm，IPC低密度)
footprint RESC1005[0402]S-L (0402贴片电阻 有丝印 2脚 1.00x0.50mm，IPC高密度)
footprint RESC1005[0402]S-M (0402贴片电阻 有丝印 2脚 1.00x0.50mm，IPC低密度)
footprint RESC1005[0402]S-N (0402贴片电阻 有丝印 2脚 1.00x0.50mm，IPC中等密度)
footprint RESC2012[0805]S-L (Silkscreen Outside, Chip Resistor, 2-Leads, Body 2.00x1.25mm, IPC Medium Density)
footprint RESC2012[0805]S-M (Silkscreen Outside, Chip Resistor, 2-Leads, Body 2.00x1.25mm, IPC Medium Density)
footprint RESC2012[0805]S-N (Silkscreen Outside, Chip Resistor, 2-Leads, Body 2.00x1.25mm, IPC Medium Density)
footprint RESC3216[1206]S-L (Silkscreen Outside, Chip Resistor, 2-Leads, Body 3.20x1.60mm, IPC Medium Density)
footprint RESC3216[1206]S-M (Silkscreen Outside, Chip Resistor, 2-Leads, Body 3.20x1.60mm, IPC Medium Density)
footprint RESC3216[1206]S-N (Silkscreen Outside, Chip Resistor, 2-Leads, Body 3.20x1.60mm, IPC Medium Density)
pins: 1, 2
1 alternate drawing of the same symbol

## Res-Chip_7
designator R?, comment value 100R  (hidden comment: 100R ±1%)
贴片电阻
footprint RESC3225[1210]S (Silkscreen Outside, Chip Resistor, 2-Leads, Body 3.20x2.49mm, IPC Medium Density)
footprint RESC5025[2010]S (Silkscreen Outside, Chip Resistor, 2-Leads, Body 5.00x2.50mm, IPC Medium Density)
footprint RESC6332[2512]S (Silkscreen Outside, Chip Resistor, 2-Leads, Body 6.30x3.20mm, IPC Medium Density)
footprint RESC5025[2010] (Chip Resistor, 2-Leads, Body 5.00x2.50mm, IPC Medium Density)
footprint RESC6332[2512] (Chip Resistor, 2-Leads, Body 6.30x3.20mm, IPC Medium Density)
footprint RESC3225[1210] (Chip Resistor, 2-Leads, Body 3.20x2.49mm, IPC Medium Density)
footprint RESC3216[1206] (Chip Resistor, 2-Leads, Body 3.20x1.60mm, IPC Medium Density)
footprint RESC2012[0805] (Chip Resistor, 2-Leads, Body 2.00x1.25mm, IPC Medium Density)
footprint RESC1608[0603]-M (Chip Resistor, 2-Leads, Body 1.60x0.82mm, IPC Maximum Density)
footprint RESC1608[0603]-L (Chip Resistor, 2-Leads, Body 1.60x0.82mm, IPC Minimum Density)
footprint RESC1608[0603]-N (Chip Resistor, 2-Leads, Body 1.60x0.82mm, IPC Medium Density)
footprint RESC1608[0603]S-L (Silkscreen Outside, Chip Resistor, 2-Leads, Body 1.60x0.82mm, IPC Minimum Density)
footprint RESC1608[0603]S-M (Silkscreen Outside, Chip Resistor, 2-Leads, Body 1.60x0.82mm, IPC Maximum Density)
footprint RESC1608[0603]S-N (Silkscreen Outside, Chip Resistor, 2-Leads, Body 1.60x0.82mm, IPC Medium Density)
footprint RESC1005[0402]-L (0402贴片电阻 无丝印 2脚 1.00x0.50mm，IPC高密度)
footprint RESC1005[0402]-N (0402贴片电阻 无丝印 2脚 1.00x0.50mm，IPC中密度)
footprint RESC1005[0402]-M (0402贴片电阻 无丝印 2脚 1.00x0.50mm，IPC低密度)
footprint RESC1005[0402]S-L (0402贴片电阻 有丝印 2脚 1.00x0.50mm，IPC高密度)
footprint RESC1005[0402]S-M (0402贴片电阻 有丝印 2脚 1.00x0.50mm，IPC低密度)
footprint RESC1005[0402]S-N (0402贴片电阻 有丝印 2脚 1.00x0.50mm，IPC中等密度)
footprint RESC2012[0805]S-L (Silkscreen Outside, Chip Resistor, 2-Leads, Body 2.00x1.25mm, IPC Medium Density)
footprint RESC2012[0805]S-M (Silkscreen Outside, Chip Resistor, 2-Leads, Body 2.00x1.25mm, IPC Medium Density)
footprint RESC2012[0805]S-N (Silkscreen Outside, Chip Resistor, 2-Leads, Body 2.00x1.25mm, IPC Medium Density)
footprint RESC3216[1206]S-L (Silkscreen Outside, Chip Resistor, 2-Leads, Body 3.20x1.60mm, IPC Medium Density)
footprint RESC3216[1206]S-M (Silkscreen Outside, Chip Resistor, 2-Leads, Body 3.20x1.60mm, IPC Medium Density)
footprint RESC3216[1206]S-N (Silkscreen Outside, Chip Resistor, 2-Leads, Body 3.20x1.60mm, IPC Medium Density)
pins: 1, 2
1 alternate drawing of the same symbol

## Res-Chip_8
designator R?, comment value 4.7K(DNP)  (hidden comment: 4.7K(DNP) ±1%)  (no BOM)
贴片电阻
footprint RESC3225[1210]S (Silkscreen Outside, Chip Resistor, 2-Leads, Body 3.20x2.49mm, IPC Medium Density)
footprint RESC5025[2010]S (Silkscreen Outside, Chip Resistor, 2-Leads, Body 5.00x2.50mm, IPC Medium Density)
footprint RESC6332[2512]S (Silkscreen Outside, Chip Resistor, 2-Leads, Body 6.30x3.20mm, IPC Medium Density)
footprint RESC5025[2010] (Chip Resistor, 2-Leads, Body 5.00x2.50mm, IPC Medium Density)
footprint RESC6332[2512] (Chip Resistor, 2-Leads, Body 6.30x3.20mm, IPC Medium Density)
footprint RESC3225[1210] (Chip Resistor, 2-Leads, Body 3.20x2.49mm, IPC Medium Density)
footprint RESC3216[1206] (Chip Resistor, 2-Leads, Body 3.20x1.60mm, IPC Medium Density)
footprint RESC2012[0805] (Chip Resistor, 2-Leads, Body 2.00x1.25mm, IPC Medium Density)
footprint RESC1608[0603]-M (Chip Resistor, 2-Leads, Body 1.60x0.82mm, IPC Maximum Density)
footprint RESC1608[0603]-L (Chip Resistor, 2-Leads, Body 1.60x0.82mm, IPC Minimum Density)
footprint RESC1608[0603]-N (Chip Resistor, 2-Leads, Body 1.60x0.82mm, IPC Medium Density)
footprint RESC1608[0603]S-L (Silkscreen Outside, Chip Resistor, 2-Leads, Body 1.60x0.82mm, IPC Minimum Density)
footprint RESC1608[0603]S-M (Silkscreen Outside, Chip Resistor, 2-Leads, Body 1.60x0.82mm, IPC Maximum Density)
footprint RESC1608[0603]S-N (Silkscreen Outside, Chip Resistor, 2-Leads, Body 1.60x0.82mm, IPC Medium Density)
footprint RESC1005[0402]-L (0402贴片电阻 无丝印 2脚 1.00x0.50mm，IPC高密度)
footprint RESC1005[0402]-N (0402贴片电阻 无丝印 2脚 1.00x0.50mm，IPC中密度)
footprint RESC1005[0402]-M (0402贴片电阻 无丝印 2脚 1.00x0.50mm，IPC低密度)
footprint RESC1005[0402]S-L (0402贴片电阻 有丝印 2脚 1.00x0.50mm，IPC高密度)
footprint RESC1005[0402]S-M (0402贴片电阻 有丝印 2脚 1.00x0.50mm，IPC低密度)
footprint RESC1005[0402]S-N (0402贴片电阻 有丝印 2脚 1.00x0.50mm，IPC中等密度)
footprint RESC2012[0805]S-L (Silkscreen Outside, Chip Resistor, 2-Leads, Body 2.00x1.25mm, IPC Medium Density)
footprint RESC2012[0805]S-M (Silkscreen Outside, Chip Resistor, 2-Leads, Body 2.00x1.25mm, IPC Medium Density)
footprint RESC2012[0805]S-N (Silkscreen Outside, Chip Resistor, 2-Leads, Body 2.00x1.25mm, IPC Medium Density)
footprint RESC3216[1206]S-L (Silkscreen Outside, Chip Resistor, 2-Leads, Body 3.20x1.60mm, IPC Medium Density)
footprint RESC3216[1206]S-M (Silkscreen Outside, Chip Resistor, 2-Leads, Body 3.20x1.60mm, IPC Medium Density)
footprint RESC3216[1206]S-N (Silkscreen Outside, Chip Resistor, 2-Leads, Body 3.20x1.60mm, IPC Medium Density)
pins: 1, 2
1 alternate drawing of the same symbol

## Res-Chip_9
designator R?, comment value 10R  (hidden comment: 10R ±1%)
贴片电阻
footprint RESC3225[1210]S (Silkscreen Outside, Chip Resistor, 2-Leads, Body 3.20x2.49mm, IPC Medium Density)
footprint RESC5025[2010]S (Silkscreen Outside, Chip Resistor, 2-Leads, Body 5.00x2.50mm, IPC Medium Density)
footprint RESC6332[2512]S (Silkscreen Outside, Chip Resistor, 2-Leads, Body 6.30x3.20mm, IPC Medium Density)
footprint RESC5025[2010] (Chip Resistor, 2-Leads, Body 5.00x2.50mm, IPC Medium Density)
footprint RESC6332[2512] (Chip Resistor, 2-Leads, Body 6.30x3.20mm, IPC Medium Density)
footprint RESC3225[1210] (Chip Resistor, 2-Leads, Body 3.20x2.49mm, IPC Medium Density)
footprint RESC3216[1206] (Chip Resistor, 2-Leads, Body 3.20x1.60mm, IPC Medium Density)
footprint RESC2012[0805] (Chip Resistor, 2-Leads, Body 2.00x1.25mm, IPC Medium Density)
footprint RESC1608[0603]-M (Chip Resistor, 2-Leads, Body 1.60x0.82mm, IPC Maximum Density)
footprint RESC1608[0603]-L (Chip Resistor, 2-Leads, Body 1.60x0.82mm, IPC Minimum Density)
footprint RESC1608[0603]-N (Chip Resistor, 2-Leads, Body 1.60x0.82mm, IPC Medium Density)
footprint RESC1608[0603]S-L (Silkscreen Outside, Chip Resistor, 2-Leads, Body 1.60x0.82mm, IPC Minimum Density)
footprint RESC1608[0603]S-M (Silkscreen Outside, Chip Resistor, 2-Leads, Body 1.60x0.82mm, IPC Maximum Density)
footprint RESC1608[0603]S-N (Silkscreen Outside, Chip Resistor, 2-Leads, Body 1.60x0.82mm, IPC Medium Density)
footprint RESC1005[0402]-L (0402贴片电阻 无丝印 2脚 1.00x0.50mm，IPC高密度)
footprint RESC1005[0402]-N (0402贴片电阻 无丝印 2脚 1.00x0.50mm，IPC中密度)
footprint RESC1005[0402]-M (0402贴片电阻 无丝印 2脚 1.00x0.50mm，IPC低密度)
footprint RESC1005[0402]S-L (0402贴片电阻 有丝印 2脚 1.00x0.50mm，IPC高密度)
footprint RESC1005[0402]S-M (0402贴片电阻 有丝印 2脚 1.00x0.50mm，IPC低密度)
footprint RESC1005[0402]S-N (0402贴片电阻 有丝印 2脚 1.00x0.50mm，IPC中等密度)
footprint RESC2012[0805]S-L (Silkscreen Outside, Chip Resistor, 2-Leads, Body 2.00x1.25mm, IPC Medium Density)
footprint RESC2012[0805]S-M (Silkscreen Outside, Chip Resistor, 2-Leads, Body 2.00x1.25mm, IPC Medium Density)
footprint RESC2012[0805]S-N (Silkscreen Outside, Chip Resistor, 2-Leads, Body 2.00x1.25mm, IPC Medium Density)
footprint RESC3216[1206]S-L (Silkscreen Outside, Chip Resistor, 2-Leads, Body 3.20x1.60mm, IPC Medium Density)
footprint RESC3216[1206]S-M (Silkscreen Outside, Chip Resistor, 2-Leads, Body 3.20x1.60mm, IPC Medium Density)
footprint RESC3216[1206]S-N (Silkscreen Outside, Chip Resistor, 2-Leads, Body 3.20x1.60mm, IPC Medium Density)
pins: 1, 2
1 alternate drawing of the same symbol

## Res-Chip_10
designator R?, comment value 470R  (hidden comment: 470R ±1%)
贴片电阻
footprint RESC3225[1210]S (Silkscreen Outside, Chip Resistor, 2-Leads, Body 3.20x2.49mm, IPC Medium Density)
footprint RESC5025[2010]S (Silkscreen Outside, Chip Resistor, 2-Leads, Body 5.00x2.50mm, IPC Medium Density)
footprint RESC6332[2512]S (Silkscreen Outside, Chip Resistor, 2-Leads, Body 6.30x3.20mm, IPC Medium Density)
footprint RESC5025[2010] (Chip Resistor, 2-Leads, Body 5.00x2.50mm, IPC Medium Density)
footprint RESC6332[2512] (Chip Resistor, 2-Leads, Body 6.30x3.20mm, IPC Medium Density)
footprint RESC3225[1210] (Chip Resistor, 2-Leads, Body 3.20x2.49mm, IPC Medium Density)
footprint RESC3216[1206] (Chip Resistor, 2-Leads, Body 3.20x1.60mm, IPC Medium Density)
footprint RESC2012[0805] (Chip Resistor, 2-Leads, Body 2.00x1.25mm, IPC Medium Density)
footprint RESC1608[0603]-M (Chip Resistor, 2-Leads, Body 1.60x0.82mm, IPC Maximum Density)
footprint RESC1608[0603]-L (Chip Resistor, 2-Leads, Body 1.60x0.82mm, IPC Minimum Density)
footprint RESC1608[0603]-N (Chip Resistor, 2-Leads, Body 1.60x0.82mm, IPC Medium Density)
footprint RESC1608[0603]S-L (Silkscreen Outside, Chip Resistor, 2-Leads, Body 1.60x0.82mm, IPC Minimum Density)
footprint RESC1608[0603]S-M (Silkscreen Outside, Chip Resistor, 2-Leads, Body 1.60x0.82mm, IPC Maximum Density)
footprint RESC1608[0603]S-N (Silkscreen Outside, Chip Resistor, 2-Leads, Body 1.60x0.82mm, IPC Medium Density)
footprint RESC1005[0402]-L (0402贴片电阻 无丝印 2脚 1.00x0.50mm，IPC高密度)
footprint RESC1005[0402]-N (0402贴片电阻 无丝印 2脚 1.00x0.50mm，IPC中密度)
footprint RESC1005[0402]-M (0402贴片电阻 无丝印 2脚 1.00x0.50mm，IPC低密度)
footprint RESC1005[0402]S-L (0402贴片电阻 有丝印 2脚 1.00x0.50mm，IPC高密度)
footprint RESC1005[0402]S-M (0402贴片电阻 有丝印 2脚 1.00x0.50mm，IPC低密度)
footprint RESC1005[0402]S-N (0402贴片电阻 有丝印 2脚 1.00x0.50mm，IPC中等密度)
footprint RESC2012[0805]S-L (Silkscreen Outside, Chip Resistor, 2-Leads, Body 2.00x1.25mm, IPC Medium Density)
footprint RESC2012[0805]S-M (Silkscreen Outside, Chip Resistor, 2-Leads, Body 2.00x1.25mm, IPC Medium Density)
footprint RESC2012[0805]S-N (Silkscreen Outside, Chip Resistor, 2-Leads, Body 2.00x1.25mm, IPC Medium Density)
footprint RESC3216[1206]S-L (Silkscreen Outside, Chip Resistor, 2-Leads, Body 3.20x1.60mm, IPC Medium Density)
footprint RESC3216[1206]S-M (Silkscreen Outside, Chip Resistor, 2-Leads, Body 3.20x1.60mm, IPC Medium Density)
footprint RESC3216[1206]S-N (Silkscreen Outside, Chip Resistor, 2-Leads, Body 3.20x1.60mm, IPC Medium Density)
pins: 1, 2
1 alternate drawing of the same symbol

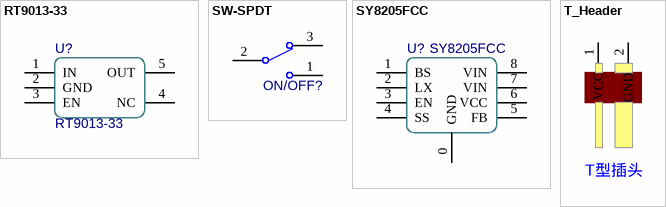
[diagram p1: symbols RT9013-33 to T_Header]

## RT9013-33
designator U?
3.3V 500mA SOT-23-5 LDO
footprint SOT-23-5 (SOT23, 5-Leads, Body 2.92x2.79mm, Pitch 0.95mm, IPC Medium Density)
pins: 1 IN, 2 GND, 3 EN, 4 NC, 5 OUT

## SW-SPDT
designator ON/OFF?  (value not drawn)
单刀双掷开关 3脚船型、钮子、拨动开关 SPDT Subminiature Toggle Switch
footprint ToggleSwitch 7102
footprint SS12D06 (拨动开关，弯脚，脚距4.8)
footprint SS12D10 (拨动开关 直脚 脚距4.8)
footprint SS12D07VG4
footprint MSK-12C02 (MSK-12C02 侧贴2档7脚开关 带定位柱)
pins: 1, 2, 3

## SY8205FCC
designator U?
同步buck
footprint SOP-8E (SOIC,1.27mm pitch;8 pin,3.90mm W X 4.88mm L X 1.73mm H body)
pins: 0 GND, 1 BS, 2 LX, 3 EN, 4 SS, 5 FB, 6 VCC, 7 VIN, 8 VIN

## T_Header
designator DCIN?, comment T型插头
footprint T_DC
footprint Wired T-Header (带线T头贴片焊盘)
footprint Wired T-Header ThroughHole (带线T头直插焊盘)
pins: 1 VCC, 2 GND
